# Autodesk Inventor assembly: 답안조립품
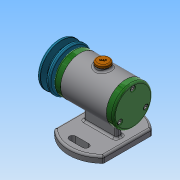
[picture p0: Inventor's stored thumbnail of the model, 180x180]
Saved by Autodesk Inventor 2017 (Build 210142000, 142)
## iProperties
Part Number: 답안조립품
Material: 일반
Document SubType Name: Assembly
Designer: user
Author: user
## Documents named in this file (14)
- C:\Users\user\Desktop\710906V1004\답안조립품.iam
- C:\Users\user\Desktop\710906V1004\1.본체.ipt
- C:\Users\user\Desktop\710906V1004\베어링 15x32x9.ipt
- C:\Users\user\Desktop\710906V1004\축.ipt
- C:\Users\user\Desktop\710906V1004\캡.ipt
- C:\Users\user\Desktop\710906V1004\뒤커버.ipt
- C:\Users\user\Desktop\710906V1004\오일 실 15x25x7.ipt
- C:\Users\user\Desktop\710906V1004\앞커버.ipt
- C:\Users\user\Desktop\710906V1004\볼트 M4x12.ipt
- C:\Users\user\Desktop\710906V1004\키 3x3.ipt
- C:\Users\user\Desktop\710906V1004\V벨트풀리.ipt
- C:\Users\user\Desktop\710906V1004\너트 M8.ipt
- C:\Users\user\Desktop\710906V1004\와셔 8x17.ipt
- C:\Users\user\Desktop\710906V1004\스프링와셔 8.ipt
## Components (2 placed, 2 different names)
1. 1.본체:1
2. V벨트풀리:1 — 각도:2
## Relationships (1: Angle 1)
- 각도:2 [Angle]: V벨트풀리:1
